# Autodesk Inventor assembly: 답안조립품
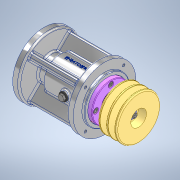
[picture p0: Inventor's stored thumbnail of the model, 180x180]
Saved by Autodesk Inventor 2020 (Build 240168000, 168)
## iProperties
Created: 2024-10
Part Number: 답안조립품
Document SubType Name: Assembly
Designer: oem
Author: oem
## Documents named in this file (18)
- C:\Users\oem\Desktop\741004V1010\답안조립품.iam
- C:\Users\oem\Desktop\741004V1010\V 벨트 풀리.ipt
- C:\Users\oem\Desktop\741004V1010\가스켓.ipt
- C:\Users\oem\Desktop\741004V1010\깊은 홈 볼베어링 6004.ipt
- C:\Users\oem\Desktop\741004V1010\스러스트 볼베어링 512 02.ipt
- C:\Users\oem\Desktop\741004V1010\스프링와셔 M5.ipt
- C:\Users\oem\Desktop\741004V1010\실링 패드.ipt
- C:\Users\oem\Desktop\741004V1010\어뎁터.ipt
- C:\Users\oem\Desktop\741004V1010\엔드캡.ipt
- C:\Users\oem\Desktop\741004V1010\오일 실 20 35 8.ipt
- C:\Users\oem\Desktop\741004V1010\육각 머리 볼트 M6x0.75x12.ipt
- C:\Users\oem\Desktop\741004V1010\육각 소켓 머리 볼트 M5x10.ipt
- C:\Users\oem\Desktop\741004V1010\축.ipt
- C:\Users\oem\Desktop\741004V1010\칼라.ipt
- C:\Users\oem\Desktop\741004V1010\커버.ipt
- C:\Users\oem\Desktop\741004V1010\평와셔 M5.ipt
- C:\Users\oem\Desktop\741004V1010\평행키 5x5x22.ipt
- C:\Users\oem\Desktop\741004V1010\본체.ipt
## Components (2 placed, 2 different names)
1. 가스켓:1
2. V 벨트 풀리:1
